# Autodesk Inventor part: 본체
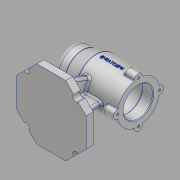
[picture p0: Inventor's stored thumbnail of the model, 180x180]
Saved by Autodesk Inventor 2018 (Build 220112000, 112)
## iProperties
Created: 2021-01
Part Number: 본체
Material: 알루미늄 6061
Document SubType Name: Modeling
Designer: home
Density: 2.7 g/cm^3
Appearance: 알루미늄 - 평지
Mass: 629.962 g
Surface Area: 613.777 cm^2
Volume: 233.319 cm^3
Author: home
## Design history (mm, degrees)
sketch "스케치1"
  geometry: L1 (20.711, -50)-(-20.711, -50); L2 (-20.711, -50)-(-50, -20.711); L3 (-50, -20.711)-(-50, 20.711); L4 (-50, 20.711)-(-20.711, 50); L5 (-20.711, 50)-(20.711, 50); L6 (20.711, 50)-(50, 20.711); L7 (50, 20.711)-(50, -20.711); L8 (50, -20.711)-(20.711, -50); C1 r 50 at (0, 0); 2 further points
  constraints: 16 end point, 2 coincident, 1 centre point, 1 horizontal alignment, 1 tangent, 17 other
  dimensions: "d0" = 100 diameter of C1
extrude "돌출1" new body sketch "스케치1" distance "d1" = 10; taper "d2" = 0 deg
sketch "스케치2" dims "d3" = 100
  geometry: L1 (0, 0)-(50, 0); L2 (50, 20.711)-(20.711, 50) reference; C1 r 4.5 at (35.355, 35.355); 1 further point
  constraints: 2 end point, 1 centre point, 1 coincident, 1 horizontal, 1 horizontal alignment, 1 midpoint, 2 other
  dimensions: "d4" = 9 diameter of C1
extrude "돌출2" cut sketch "스케치2" distance "d5" = 10; taper "d6" = 0 deg
sketch "스케치3"
  geometry: L1 (50, 75)-(-50, 75); L2 (-50, 75)-(-50, 100); L3 (-50, 100)-(-30, 100); L4 (-30, 100)-(-10, 105); L5 (-10, 105)-(50, 105); L6 (50, 105)-(50, 96); L7 (-44, 75)-(-44, 85.5); L8 (-44, 85.5)-(-41, 85.5); L9 (-41, 85.5)-(-41, 91); L10 (-41, 91)-(-37, 91); L11 (-37, 91)-(-37, 92.5); L12 (-37, 92.5)-(-19, 92.5); L13 (-19, 92.5)-(-19, 96); L14 (-19, 96)-(-7, 96); L15 (-7, 96)-(-7, 99); L16 (-7, 99)-(35, 99); L17 (35, 99)-(35, 96); L18 (35, 96)-(50, 96); 1 further point
  constraints: 36 end point, 12 perpendicular, 2 point on line, 2 vertical, 1 horizontal, 1 horizontal alignment, 1 parallel, 1 vertical alignment
  dimensions: "d10" = 100 distance of L1.start L1.end; "d11" = 75 vertical distance of point (0, 0) L1.start; "d12" = 50 horizontal distance of point (0, 0) L1.start; "d13" = 60 diameter of L5 L1; "d14" = 50 diameter of L3 L1; "d15" = 20 distance of L3.end L2.end; "d16" = 40 horizontal distance of L4.end L2.end; "d17" = 3 distance between parallel lines of L9 L7; "d18" = 4 distance between parallel lines of L11 L9; "d19" = 18 distance between parallel lines of L13 L11; "d20" = 12 distance between parallel lines of L15 L13; "d21" = 42 distance between parallel lines of L17 L15; "d22" = 15 distance of L17.end L6.end; "d23" = 21 diameter of L8 L1; "d24" = 32 diameter of L10 L1; "d25" = 35 diameter of L12 L1; "d26" = 42 diameter of L14 L1; "d27" = 48 diameter of L16 L1
revolve "회전1" sketch "스케치3" stored, may be unused: angle "d28" = 90 deg
fillet "모깎기1" dims "d29" = 10, "d30" = 3, "d31" = 0.3
sketch "스케치4"
  geometry: L1 (-27, -4)-(27, -4); L2 (27, -4)-(27, 4); L3 (27, 4)-(-27, 4); L4 (-27, 4)-(-27, -4); L5 (-27, -4)-(27, 4); L6 (27, -4)-(-27, 4); L7 (50, 20.711)-(50, -20.711) reference; 1 further point
  constraints: 12 end point, 2 midpoint, 2 parallel, 1 horizontal, 1 perpendicular
  dimensions: "d32" = 23 distance between parallel lines of L7 L2; "d33" = 8 distance of L3.end L1.start
extrude "돌출3" join sketch "스케치4" stored distance "d34" = 10; taper "d35" = 0 deg
feature "면 기울기1" dims angle "d36" = 11 deg
sketch "스케치5"
  geometry: L1 (10, 38.537)-(10, 30.855) reference; L2 (10, 35)-(52.786, 19.427); L3 (0, 50)-(10, 50) reference; 1 further point
  constraints: 2 end point, 1 point on line
  dimensions: "d37" = 15 distance from line of L2.start L3; "d38" = 110 deg angle of L1 L2
feature "리브1" sketch "스케치5" dims "d39" = 1, "d40" = 8, "d41" = 0, "d42" = 0, "d43" = 1, "d44" = 1
sketch "스케치6"
  geometry: A1 r 6 centre (0, 30) between (5.97, 29.4) and (-5.97, 29.4); A2 r 30 centre (0, 0) between (0, 30) and (-5.97, 29.4) reference; A3 r 30 centre (0, 0) between (5.97, 29.4) and (-5.97, 29.4); 1 further point
  constraints: 8 point on circle, 2 centre point, 1 coincident, 1 vertical alignment
  dimensions: "d45" = 6 radius of A1
extrude "돌출4" join sketch "스케치6" distance "d46" = 16; taper "d47" = 0 deg
sketch "스케치7"
  geometry: A1 r 6 centre (0, 0) between (5.97, -0.6) and (-5.97, -0.6) reference; 2 further points
  constraints: 1 coincident
hole "구멍1" sketch "스케치7" at (0, 0) diameter "d48" = 3.242; stored, may be unused: countersink angle "d52" = 90 deg, drill point angle "d54" = 118 deg; dims "d49" = 8, "d50" = 4, "d51" = 2, "d53" = 10
fillet "모깎기2" dims "d55" = 3
fillet "모깎기3" dims "d56" = 1
fillet "모깎기4" dims "d60" = 3
fillet "모깎기5" dims "d61" = 3
node "작업 평면1"
sketch "스케치8"
  geometry: L1 (50, 81.771)-(50, 104.226) reference; 2 further points
  constraints: 1 other
  dimensions: "d63" = 38 distance from line of L1 point (12, 75); "d64" = 75 vertical distance of point (0, 0) point (12, 75)
feature "엠보싱1" sketch "스케치8" dims "d0" = 100, "d65" = 0.5, "d66" = 0
chamfer "모따기1" distance "d67" = 1; stored, may be unused: second distance "d68" = 2, angle "d69" = 45 deg
node "솔리드1"
pattern_circular "원형 패턴1" dims angle "d8" = 360 deg
mirror "미러1"
pattern_circular "원형 패턴2" dims "d58" = 360 deg
